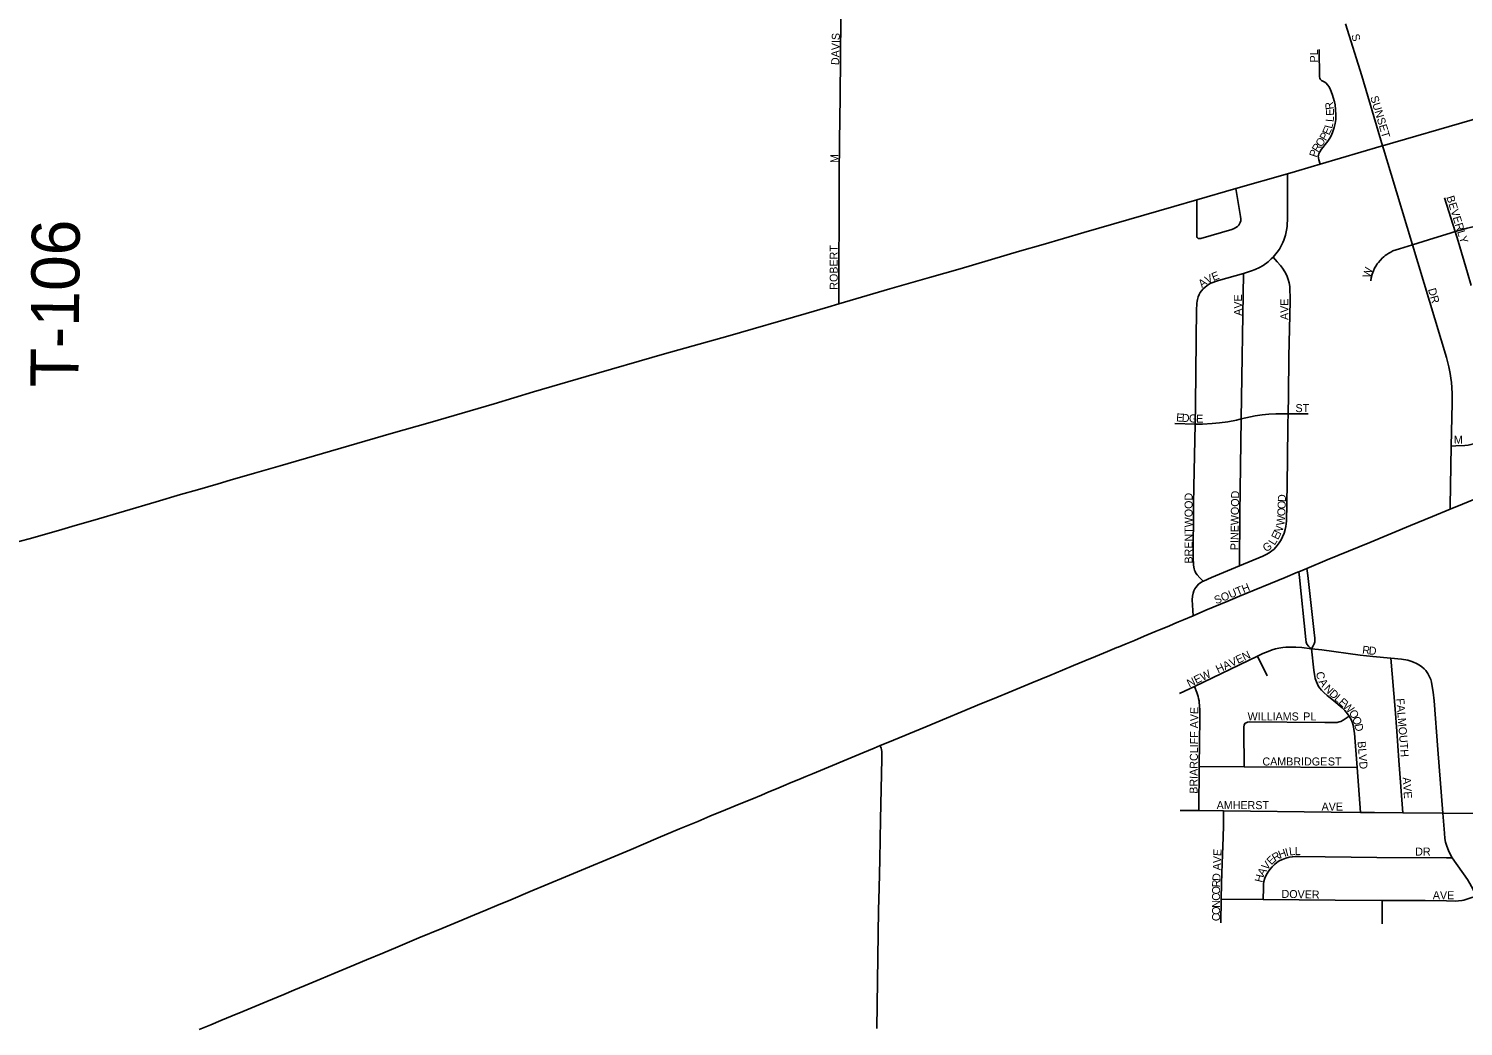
# Model space of a CAD drawing. Extents: x -87 to 2145, y -2128 to 440.
# Drawn here: x 221.2 to 266.02, y -585.43 to -554.25 of the extents above; entities that cross this region are included whole.
import ezdxf

# ---------------------------------------------------------------- set-up
doc = ezdxf.new("R2010")
doc.units = 0
for name, color, linetype in [('GM_X_City_Street', 7, 'Continuous'), ('GM_X_City_Street_Text', 7, 'Continuous'), ('GM_X_County_Road', 7, 'Continuous'), ('GM_X_Township_Road', 7, 'Continuous'), ('GM_X_Township_Road_Text', 7, 'Continuous'), ('GM_X_US_Route', 7, 'Continuous')]:
    doc.layers.add(name, color=color, linetype=linetype)

msp = doc.modelspace()

# ---------------------------------------------------------------- linework, layer by layer
at = {"layer": 'GM_X_City_Street'}
for points in [[(246.518, -558.848), (246.533, -557.76), (246.547, -556.383), (246.571, -553.906), (246.599, -551.215), (246.602, -550.749)], [(263.498, -557.91), (262.847, -555.727), (262.344, -554.099)], [(261.543, -558.487), (261.501, -558.343), (261.491, -558.283), (261.488, -558.234), (261.495, -558.201), (261.511, -558.155), (261.54, -558.097), (261.594, -558.015), (261.785, -557.769), (261.849, -557.674), (261.903, -557.573), (261.948, -557.467), (261.987, -557.342), (262.015, -557.214), (262.033, -557.085), (262.039, -556.954), (262.031, -556.774), (262.014, -556.627), (261.994, -556.531), (261.92, -556.297), (261.87, -556.158), (261.826, -556.07), (261.781, -556.002), (261.737, -555.954), (261.698, -555.924), (261.59, -555.863), (261.551, -555.83), (261.534, -555.791), (261.524, -555.75), (261.521, -554.898)], [(264.428, -561.009), (263.761, -558.793), (263.527, -558.007), (263.498, -557.91)], [(246.504, -562.85), (246.517, -558.974), (246.518, -558.848)], [(260.077, -561.385), (260.123, -561.339), (260.206, -561.238), (260.272, -561.144), (260.334, -561.038), (260.382, -560.936), (260.412, -560.858), (260.434, -560.791), (260.464, -560.698), (260.486, -560.602), (260.506, -560.498), (260.514, -560.416), (260.521, -560.337), (260.527, -560.244), (260.531, -560.15), (260.529, -558.978), (260.528, -558.784)], [(257.694, -559.598), (257.693, -559.803), (257.689, -560.608), (257.691, -560.739), (257.694, -560.755), (257.701, -560.77), (257.711, -560.783), (257.723, -560.793), (257.738, -560.801), (257.77, -560.807), (257.818, -560.801), (258.783, -560.527), (258.859, -560.497), (258.917, -560.466), (258.969, -560.426), (259.003, -560.39), (259.032, -560.35), (259.052, -560.305), (259.064, -560.258), (259.069, -560.192), (259.061, -560.121), (258.987, -559.686), (258.914, -559.247)], [(265.761, -560.592), (265.437, -559.531)], [(264.428, -561.009), (265.102, -560.792), (265.61, -560.636), (265.761, -560.592)], [(265.761, -560.592), (265.924, -560.545), (266.035, -560.512), (266.139, -560.484), (266.23, -560.46), (266.319, -560.441), (266.406, -560.423), (266.512, -560.404), (266.601, -560.389), (266.718, -560.371), (266.799, -560.36), (266.881, -560.349), (266.981, -560.339), (267.081, -560.33), (267.181, -560.323), (267.272, -560.319), (267.378, -560.315), (267.491, -560.315), (267.626, -560.313), (267.771, -560.315), (268.023, -560.319), (268.613, -560.33), (269.538, -560.345), (270.154, -560.349)], [(266.27, -562.278), (266.15, -561.879), (265.854, -560.894), (265.761, -560.592)], [(263.128, -562.129), (263.143, -562.032), (263.171, -561.921), (263.21, -561.813), (263.248, -561.734), (263.287, -561.669), (263.328, -561.603), (263.365, -561.556), (263.419, -561.491), (263.493, -561.415), (263.532, -561.378), (263.582, -561.334), (263.631, -561.301), (263.693, -561.261), (263.751, -561.23), (263.823, -561.195), (263.917, -561.159), (264.021, -561.124), (264.428, -561.009)], [(265.64, -567.294), (265.67, -565.953), (265.671, -565.657), (265.662, -565.461), (265.65, -565.311), (265.633, -565.167), (265.61, -565.021), (265.566, -564.813), (265.491, -564.527), (264.428, -561.009)], [(259.148, -561.896), (259.403, -561.82), (259.518, -561.778), (259.651, -561.716), (259.764, -561.649), (259.921, -561.531), (260.02, -561.445), (260.077, -561.385)], [(260.545, -566.284), (260.553, -565.718), (260.57, -564.491), (260.606, -562.767), (260.607, -562.603), (260.604, -562.456), (260.595, -562.309), (260.577, -562.196), (260.548, -562.085), (260.501, -561.963), (260.443, -561.846), (260.375, -561.734), (260.311, -561.645), (260.209, -561.532), (260.077, -561.385)], [(257.641, -566.608), (257.654, -565.997), (257.685, -562.986), (257.689, -562.898), (257.693, -562.823), (257.702, -562.762), (257.711, -562.709), (257.733, -562.63), (257.765, -562.558), (257.799, -562.492), (257.836, -562.44), (257.891, -562.38), (257.951, -562.325), (258.003, -562.284), (258.062, -562.245), (258.136, -562.204), (258.197, -562.178), (258.277, -562.147), (258.37, -562.116), (259.148, -561.896)], [(259.082, -566.446), (259.148, -561.896)], [(257.641, -566.608), (257.876, -566.607), (258.177, -566.591), (258.4, -566.569), (258.66, -566.532), (258.934, -566.48), (259.082, -566.446)], [(259.028, -571.034), (259.753, -570.731), (259.886, -570.667), (259.984, -570.607), (260.05, -570.562), (260.098, -570.521), (260.165, -570.449), (260.207, -570.397), (260.266, -570.319), (260.327, -570.222), (260.373, -570.135), (260.422, -570.016), (260.455, -569.906), (260.475, -569.807), (260.486, -569.724), (260.492, -569.632), (260.503, -569.124), (260.526, -567.732), (260.541, -566.603), (260.545, -566.284)], [(259.028, -571.034), (259.037, -569.398), (259.082, -566.446)], [(259.082, -566.446), (259.519, -566.352), (259.731, -566.318), (259.942, -566.296), (260.161, -566.285), (260.545, -566.284)], [(260.545, -566.284), (261.177, -566.29)], [(257.007, -566.589), (257.641, -566.608)], [(257.889, -571.518), (257.789, -571.409), (257.706, -571.315), (257.667, -571.261), (257.643, -571.214), (257.626, -571.169), (257.613, -571.125), (257.601, -571.079), (257.591, -571.008), (257.585, -570.934), (257.582, -570.844), (257.595, -569.107), (257.6, -568.567), (257.641, -566.608)], [(265.64, -567.294), (265.786, -567.288), (266.064, -567.276), (266.174, -567.264), (266.259, -567.246), (266.386, -567.214), (266.555, -567.164), (267.088, -566.939), (267.093, -566.937)], [(265.609, -569.27), (265.611, -569.166), (265.64, -567.294)], [(265.609, -569.27), (265.997, -569.112), (266.528, -568.893), (267.468, -568.509), (268.212, -568.204), (268.788, -567.966), (269.734, -567.579)], [(261.131, -571.116), (261.767, -570.854), (263.101, -570.304), (264.374, -569.778), (265.059, -569.493), (265.609, -569.27)], [(257.889, -571.518), (257.899, -571.513), (258.149, -571.398), (259.028, -571.034)], [(257.578, -572.597), (257.975, -572.425), (258.661, -572.14), (259.025, -571.989), (260.45, -571.401), (260.843, -571.235), (260.88, -571.22)], [(260.88, -571.22), (261.131, -571.116)], [(261.281, -573.628), (261.186, -573.548), (261.134, -573.48), (261.11, -573.424), (261.095, -573.338), (260.898, -571.403), (260.88, -571.22)], [(261.281, -573.628), (261.331, -573.539), (261.362, -573.474), (261.377, -573.413), (261.381, -573.295), (261.362, -573.117), (261.157, -571.341), (261.131, -571.116)], [(257.578, -572.597), (257.554, -572.261), (257.55, -572.098), (257.558, -571.984), (257.577, -571.887), (257.602, -571.821), (257.633, -571.76), (257.659, -571.712), (257.7, -571.658), (257.745, -571.61), (257.815, -571.56), (257.889, -571.518)], [(257.125, -572.791), (257.278, -572.727), (257.578, -572.597)], [(259.587, -573.861), (259.757, -573.78), (259.922, -573.709), (260.047, -573.663), (260.154, -573.63), (260.257, -573.608), (260.38, -573.588), (260.476, -573.582), (260.576, -573.578), (260.79, -573.578), (260.974, -573.592), (261.281, -573.628)], [(262.458, -575.732), (262.406, -575.66), (262.323, -575.558), (262.23, -575.47), (261.907, -575.208), (261.765, -575.094), (261.661, -574.999), (261.592, -574.925), (261.54, -574.863), (261.499, -574.803), (261.461, -574.734), (261.43, -574.665), (261.394, -574.554), (261.366, -574.431), (261.347, -574.296), (261.281, -573.628)], [(261.281, -573.628), (261.599, -573.666), (262.802, -573.825), (263.194, -573.869), (263.759, -573.922)], [(257.621, -574.803), (259.587, -573.861)], [(259.896, -574.476), (259.587, -573.861)], [(264.129, -578.752), (264.006, -577.118), (263.94, -576.203), (263.888, -575.518), (263.759, -573.922)], [(263.759, -573.922), (264.084, -573.957), (264.288, -573.989), (264.383, -574.015), (264.463, -574.045), (264.56, -574.091), (264.646, -574.141), (264.724, -574.194), (264.799, -574.255), (264.844, -574.303), (264.872, -574.343), (264.913, -574.405), (264.947, -574.467), (264.974, -574.523), (265.003, -574.592), (265.028, -574.677), (265.049, -574.806), (265.075, -574.989), (265.106, -575.254), (265.225, -576.776), (265.38, -578.762)], [(257.148, -575.029), (257.621, -574.803)], [(257.772, -577.306), (257.788, -575.81), (257.788, -575.563), (257.777, -575.382), (257.771, -575.324), (257.762, -575.257), (257.748, -575.183), (257.733, -575.121), (257.69, -574.994), (257.621, -574.803)], [(259.177, -577.319), (259.166, -576.16), (259.166, -576.07), (259.173, -576.018), (259.187, -575.983), (259.208, -575.958), (259.234, -575.94), (259.278, -575.922), (259.328, -575.914), (261.689, -575.936), (261.952, -575.937), (262.075, -575.932), (262.146, -575.917), (262.191, -575.898), (262.261, -575.855), (262.458, -575.732)], [(262.701, -577.341), (262.619, -576.27), (262.604, -576.148), (262.588, -576.054), (262.556, -575.947), (262.514, -575.841), (262.458, -575.732)], [(257.752, -578.688), (257.772, -577.306)], [(257.772, -577.306), (259.177, -577.319)], [(259.177, -577.319), (262.701, -577.341)], [(262.809, -578.743), (262.701, -577.341)], [(257.17, -578.681), (257.752, -578.688)], [(257.752, -578.688), (258.532, -578.698)], [(258.458, -581.451), (258.463, -580.966), (258.483, -580.336), (258.517, -579.512), (258.527, -579.153), (258.53, -578.924), (258.532, -578.698)], [(258.532, -578.698), (261.896, -578.74), (262.809, -578.743)], [(262.809, -578.743), (263.24, -578.745), (264.129, -578.752)], [(264.129, -578.752), (265.38, -578.762)], [(265.38, -578.762), (266.932, -578.78)], [(265.38, -578.762), (265.427, -579.395), (265.442, -579.558), (265.464, -579.672), (265.5, -579.796), (265.553, -579.934), (265.618, -580.066), (265.672, -580.164)], [(259.768, -581.468), (259.773, -581.099), (259.781, -580.98), (259.791, -580.902), (259.818, -580.802), (259.851, -580.721), (259.889, -580.652), (259.925, -580.597), (259.98, -580.523), (260.047, -580.444), (260.125, -580.366), (260.209, -580.299), (260.288, -580.249), (260.366, -580.211), (260.474, -580.173), (260.578, -580.144), (260.679, -580.127), (260.776, -580.12), (260.906, -580.117), (263.318, -580.154), (265.495, -580.163), (265.672, -580.164)], [(265.672, -580.164), (266.146, -580.836), (266.227, -580.969), (266.323, -581.148), (266.423, -581.358)], [(258.449, -582.191), (258.458, -581.451)], [(258.458, -581.451), (259.768, -581.468)], [(259.768, -581.468), (262.021, -581.485), (263.48, -581.494)], [(263.48, -581.494), (264.824, -581.501), (265.497, -581.511), (265.775, -581.515), (265.873, -581.509), (265.977, -581.497), (266.041, -581.483), (266.227, -581.428), (266.423, -581.358)], [(263.48, -582.224), (263.48, -581.494)]]:
    msp.add_lwpolyline(points, dxfattribs=at)
at = {"layer": 'GM_X_County_Road'}
for points in [[(256.816, -572.919), (256.977, -572.852), (257.125, -572.791)], [(255.233, -573.577), (255.486, -573.473), (255.743, -573.367), (256.053, -573.238), (256.426, -573.079)], [(256.426, -573.079), (256.53, -573.035), (256.816, -572.919)], [(247.8, -576.654), (248.043, -576.554), (249.226, -576.063), (250.969, -575.342), (251.365, -575.181), (251.912, -574.955), (252.535, -574.694), (253.099, -574.46), (253.494, -574.297), (253.843, -574.154), (254.199, -574.004), (254.525, -573.87), (254.902, -573.711), (255.198, -573.592), (255.233, -573.577)], [(226.526, -585.532), (226.892, -585.378), (227.203, -585.248), (227.554, -585.102), (227.886, -584.966), (228.262, -584.809), (228.639, -584.653), (229.167, -584.432), (229.481, -584.299), (229.833, -584.152), (230.085, -584.045), (230.333, -583.94), (230.729, -583.774), (231.231, -583.566), (231.756, -583.347), (232.257, -583.138), (232.73, -582.941), (233.39, -582.667), (234.102, -582.372), (234.607, -582.162), (235.126, -581.947), (235.475, -581.802), (235.82, -581.656), (236.257, -581.474), (236.868, -581.218), (237.418, -580.988), (237.964, -580.758), (240.022, -579.902), (240.41, -579.738), (240.868, -579.542), (241.532, -579.26), (242.107, -579.022), (242.483, -578.865), (242.964, -578.666), (243.444, -578.468), (243.787, -578.325), (244.089, -578.199), (244.323, -578.101), (244.557, -578.004), (244.776, -577.913), (245.022, -577.811), (245.263, -577.709), (245.48, -577.618), (245.684, -577.533), (247.257, -576.882), (247.613, -576.732), (247.8, -576.654)]]:
    msp.add_lwpolyline(points, dxfattribs=at)
at = {"layer": 'GM_X_Township_Road'}
msp.add_lwpolyline([(247.698, -585.494), (247.752, -581.803), (247.768, -581.114), (247.787, -580.212), (247.813, -578.965), (247.848, -577.07), (247.85, -576.894), (247.848, -576.834), (247.844, -576.783), (247.828, -576.729), (247.813, -576.69), (247.8, -576.654)], dxfattribs=at)
at = {"layer": 'GM_X_US_Route'}
for points in [[(261.264, -558.569), (261.543, -558.487), (263.451, -557.923), (263.498, -557.91), (266.294, -557.098), (266.742, -556.965), (267.993, -556.594), (268.637, -556.403), (269.424, -556.17), (270.069, -555.983), (270.198, -555.945), (271.431, -555.584), (271.442, -555.581), (272.167, -555.364), (272.609, -555.235), (273.672, -554.924), (274.551, -554.656)], [(256.979, -559.803), (257.694, -559.598), (258.914, -559.247), (260.528, -558.784), (260.774, -558.714), (261.264, -558.569)], [(254.164, -560.62), (256.979, -559.803)], [(252.896, -560.989), (254.164, -560.62)], [(249.346, -562.024), (250.302, -561.749), (252.157, -561.203), (252.896, -560.989)], [(248.103, -562.381), (249.346, -562.024)], [(241.067, -564.408), (243.04, -563.856), (245.484, -563.145), (246.163, -562.95), (246.504, -562.85), (248.103, -562.381)], [(238.617, -565.119), (241.067, -564.408)], [(236.965, -565.601), (238.617, -565.119)], [(220.188, -570.482), (220.736, -570.321), (221.21, -570.188), (222.126, -569.929), (222.646, -569.777), (223.197, -569.618), (225.179, -569.031), (225.935, -568.81), (226.471, -568.658), (227.119, -568.475), (227.496, -568.364), (228.252, -568.143), (229.057, -567.915), (232.522, -566.902), (233.736, -566.556), (235.737, -565.976), (236.965, -565.601)]]:
    msp.add_lwpolyline(points, dxfattribs=at)

# ---------------------------------------------------------------- texts
at = {"layer": 'GM_X_City_Street_Text'}
for s, rotation, p in [('DAVIS', 88.6368, (246.518, -555.388)), ('S', 285.9372, (262.516, -554.453)), ('PL', 90, (261.478, -555.302)), ('R', 98.2864, (261.975, -556.759)), ('SUNSET', 286.6989, (263.11, -556.388)), ('L', 85.4159, (261.968, -557.171)), ('E', 91.7772, (261.983, -556.966)), ('P', 58.9358, (261.723, -557.772)), ('E', 65.3771, (261.828, -557.594)), ('L', 75.7724, (261.918, -557.387)), ('P', 72.2564, (261.434, -558.286)), ('R', 58.1491, (261.481, -558.133)), ('O', 54.4852, (261.583, -557.969)), ('M', 90, (246.496, -558.447)), ('BEVERLY', 287.3016, (265.486, -559.511)), ('ROBERT', 90, (246.474, -562.407)), ('V', 25.9492, (258.019, -562.231)), ('E', 21.2788, (258.212, -562.137)), ('W', 73.5326, (263.105, -562.056)), ('A', 37.342, (257.855, -562.358)), ('DR', 285.5147, (264.914, -562.395)), ('AVE', 90, (259.102, -563.221)), ('AVE', 90, (260.554, -563.353)), ('ST', 0, (260.777, -566.232)), ('E', 355.7898, (257.041, -566.519)), ('D', 355.804, (257.216, -566.531)), ('G', 356.7615, (257.44, -566.548)), ('E', 359.4676, (257.673, -566.561)), ('M', 0.9655, (265.728, -567.222)), ('BRENTWOOD', 90, (257.562, -570.965)), ('PINEWOOD', 89.2232, (258.992, -570.547)), ('O', 87.6284, (260.455, -569.487)), ('O', 87.5513, (260.464, -569.267)), ('D', 87.5608, (260.473, -569.047)), ('W', 84.2895, (260.425, -569.787)), ('E', 63.5264, (260.229, -570.24)), ('N', 65.6373, (260.311, -570.073)), ('G', 32.4595, (259.852, -570.616)), ('L', 58.1996, (260.124, -570.412)), ('SOUTH', 22.2492, (258.296, -572.242)), ('HAVEN', 25.5144, (258.359, -574.399)), ('R', 353.1852, (262.851, -573.779)), ('D', 355.0984, (263.057, -573.803)), ('NEW', 25.7697, (257.457, -574.839)), ('C', 279.1469, (261.419, -574.364)), ('A', 302.2905, (261.489, -574.662)), ('N', 314.5691, (261.643, -574.894)), ('D', 317.9808, (261.809, -575.062)), ('L', 318.0612, (261.973, -575.209)), ('BRIARCLIFF AVE', 89.493, (257.716, -578.159)), ('E', 318.0534, (262.104, -575.327)), ('W', 317.0331, (262.234, -575.444)), ('FALMOUTH', 274.3989, (263.926, -575.187)), ('WILLIAMS', 0, (259.281, -575.868)), ('PL', 0, (261.019, -575.868)), ('O', 301.4586, (262.432, -575.625)), ('O', 291.0344, (262.541, -575.802)), ('D', 281.4428, (262.617, -575.996)), ('BLVD', 274.517, (262.716, -576.528)), ('CAMBRIDGE', 0, (259.743, -577.276)), ('ST', 0, (261.789, -577.276)), ('AVE', 273.9506, (264.124, -577.65)), ('AMHERST', 0, (258.313, -578.64)), ('AVE', 0, (261.591, -578.684)), ('AVE', 88.0261, (258.442, -580.556)), ('R', 31.3594, (260.134, -580.289)), ('H', 20.0111, (260.291, -580.191)), ('I', 14.8948, (260.492, -580.118)), ('L', 6.488, (260.589, -580.091)), ('L', 0.5191, (260.757, -580.072)), ('DR', 0, (264.517, -580.092)), ('V', 50.9305, (259.887, -580.569)), ('E', 44.9227, (260.021, -580.403)), ('R', 88.3482, (258.42, -581.087)), ('D', 86.3255, (258.426, -580.892)), ('H', 76.5893, (259.738, -580.947)), ('A', 59.6885, (259.782, -580.751)), ('O', 89.9703, (258.42, -581.306)), ('C', 89.9703, (258.42, -581.504)), ('DOVER', 358.8072, (260.338, -581.412)), ('AVE', 0, (265.067, -581.456)), ('O', 89.9703, (258.42, -581.943)), ('N', 89.9703, (258.42, -581.723)), ('C', 89.9757, (258.42, -582.141))]:
    msp.add_text(s, height=0.25, rotation=rotation, dxfattribs=at).set_placement(p)
at = {"layer": 'GM_X_Township_Road_Text'}
msp.add_text('T-106', height=1.5, rotation=89.4388, dxfattribs=at).set_placement((222.747, -565.462))

doc.saveas('drawing.dxf')
